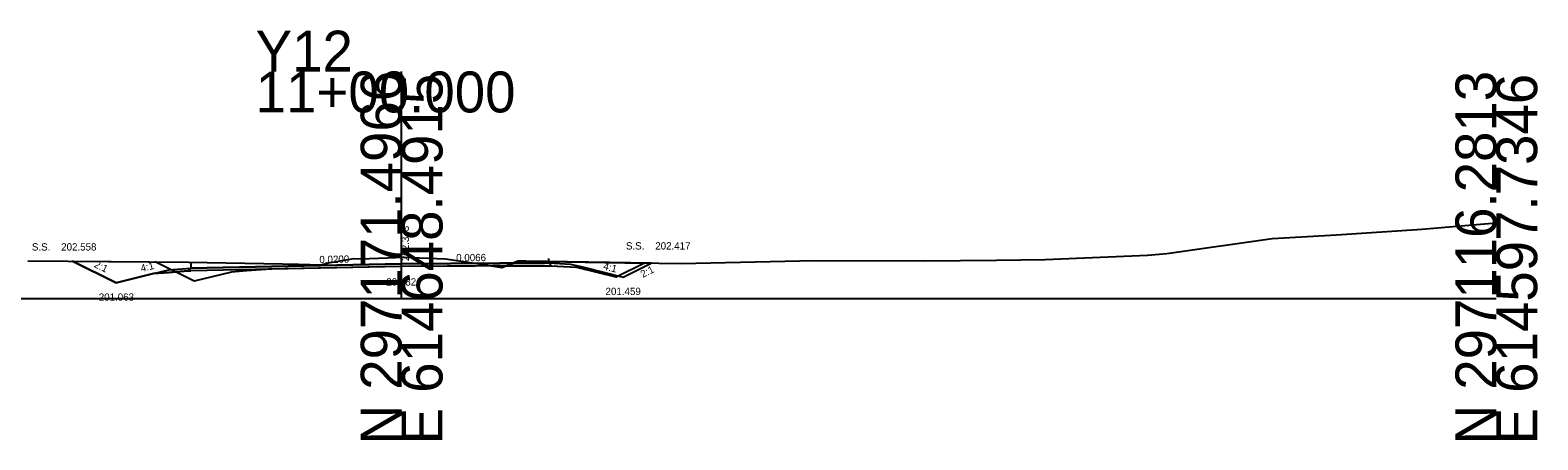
# Model space of a CAD drawing. Extents: x 517327 to 517505, y 114839 to 117367.
# Drawn here: x 517401.9 to 517505.2, y 117338.7 to 117366.8 of the extents above; entities that cross this region are included whole.
import ezdxf

# ---------------------------------------------------------------- set-up
doc = ezdxf.new("R2010")
doc.units = 0
for name, color, linetype in [('Exist XS Ground Line', 7, 'Continuous'), ('Old_Level_3', 7, 'Continuous'), ('Old_Level_5', 7, 'Continuous'), ('Old_Level_59', 7, 'Continuous'), ('Old_Level_63', 7, 'Continuous'), ('Prop XS Dump Level', 7, 'Continuous'), ('Prop XS Earthwork Shape', 7, 'Continuous'), ('Prop XS Elevation Labels', 7, 'Continuous'), ('Prop XS EOT Tick Mark', 7, 'Continuous'), ('Prop XS Finish Grade', 7, 'Continuous'), ('Prop XS Finish Grade Earthwork', 7, 'Continuous'), ('Prop XS Finish Grade Pavement', 7, 'Continuous'), ('Prop XS Hydro Elevations', 7, 'Continuous'), ('Prop XS Pvmt Edge Slope', 7, 'Continuous'), ('Prop XS Side Slope Text', 7, 'Continuous'), ('Prop XS Subgrade Earthwork', 7, 'Continuous'), ('Prop XS Suitable Common Exc Shape', 7, 'Continuous')]:
    doc.layers.add(name, color=color, linetype=linetype)

msp = doc.modelspace()

# ---------------------------------------------------------------- linework, layer by layer
at = {"layer": 'Exist XS Ground Line'}
for p, q in [((517497.25, 117353.11), (517502.36, 117353.55)), ((517479.79, 117351.44), (517487, 117352.47)), ((517487, 117352.47), (517491.4, 117352.72)), ((517491.4, 117352.72), (517497.25, 117353.11)), ((517479.27, 117351.39), (517479.79, 117351.44)), ((517401.76, 117350.95), (517412.76, 117350.85)), ((517412.76, 117350.85), (517419.2, 117350.74)), ((517419.2, 117350.74), (517420.3, 117350.71)), ((517420.3, 117350.71), (517421.87, 117350.67)), ((517421.87, 117350.67), (517422.32, 117350.8)), ((517422.32, 117350.8), (517424.09, 117351.11)), ((517424.09, 117351.11), (517424.56, 117351.08)), ((517424.56, 117351.08), (517426.37, 117351.15)), ((517426.37, 117351.15), (517427.51, 117351.19)), ((517427.51, 117351.19), (517428.61, 117351.15)), ((517428.61, 117351.15), (517430.36, 117351.09)), ((517430.36, 117351.09), (517432.35, 117350.78)), ((517432.35, 117350.78), (517434.22, 117350.49)), ((517434.22, 117350.49), (517435.35, 117350.93)), ((517435.35, 117350.93), (517435.88, 117350.92)), ((517435.88, 117350.92), (517446.52, 117350.75)), ((517446.52, 117350.75), (517455.64, 117350.96)), ((517455.64, 117350.96), (517463.16, 117350.94)), ((517463.16, 117350.94), (517468.12, 117351)), ((517468.12, 117351), (517471.46, 117351.04)), ((517471.46, 117351.04), (517478.47, 117351.34)), ((517478.47, 117351.34), (517479.27, 117351.39))]:
    msp.add_line(p, q, dxfattribs=at)
at = {"layer": 'Old_Level_63'}
for p, q in [((517427.36, 117348.36), (517427.36, 117363.92)), ((517352.36, 117348.36), (517427.36, 117348.36)), ((517427.36, 117348.36), (517502.36, 117348.36))]:
    msp.add_line(p, q, dxfattribs=at)
at = {"layer": 'Prop XS Dump Level'}
for p, q in [((517412.91, 117350.45), (517427.36, 117350.74)), ((517427.36, 117350.74), (517437.44, 117350.8))]:
    msp.add_line(p, q, dxfattribs=at)
at = {"layer": 'Prop XS Earthwork Shape'}
for points in [[(517404.82, 117350.92), (517412.76, 117350.85), (517419.2, 117350.74), (517420.3, 117350.71), (517421.87, 117350.67), (517422.32, 117350.8), (517424.09, 117351.11), (517424.56, 117351.08), (517426.37, 117351.15), (517427.51, 117351.19), (517428.61, 117351.15), (517430.36, 117351.09), (517432.35, 117350.78), (517433.58, 117350.59), (517427.36, 117350.55), (517412.91, 117350.26), (517412.72, 117350.25), (517411.41, 117350.15), (517410.36, 117350.07), (517407.81, 117349.43)], [(517434.22, 117350.49), (517434.49, 117350.59), (517433.58, 117350.59)], [(517437.44, 117350.61), (517437.62, 117350.61), (517438.94, 117350.54), (517439.84, 117350.5), (517442.54, 117349.82), (517444.45, 117350.78), (517435.88, 117350.92), (517435.35, 117350.93), (517434.49, 117350.59)]]:
    msp.add_lwpolyline(points, close=True, dxfattribs=at)
at = {"layer": 'Prop XS EOT Tick Mark'}
for p, q in [((517412.91, 117350.75), (517412.91, 117350.45)), ((517437.44, 117350.8), (517437.44, 117351.11))]:
    msp.add_line(p, q, dxfattribs=at)
at = {"layer": 'Prop XS Finish Grade'}
for p, q in [((517411.41, 117350.33), (517412.91, 117350.45)), ((517437.44, 117350.8), (517438.94, 117350.72)), ((517438.94, 117350.72), (517439.84, 117350.5)), ((517410.36, 117350.07), (517411.41, 117350.33))]:
    msp.add_line(p, q, dxfattribs=at)
at = {"layer": 'Prop XS Finish Grade Earthwork'}
for p, q in [((517404.82, 117350.92), (517407.81, 117349.43)), ((517439.84, 117350.5), (517442.54, 117349.82)), ((517442.54, 117349.82), (517444.45, 117350.78)), ((517407.81, 117349.43), (517410.36, 117350.07))]:
    msp.add_line(p, q, dxfattribs=at)
at = {"layer": 'Prop XS Finish Grade Pavement'}
for p, q in [((517427.36, 117350.74), (517412.91, 117350.45)), ((517437.44, 117350.8), (517427.36, 117350.74))]:
    msp.add_line(p, q, dxfattribs=at)
at = {"layer": 'Prop XS Pvmt Edge Slope'}
for p, q in [((517412.72, 117350.25), (517412.91, 117350.45)), ((517437.44, 117350.8), (517437.62, 117350.61))]:
    msp.add_line(p, q, dxfattribs=at)
at = {"layer": 'Prop XS Subgrade Earthwork'}
for p, q in [((517427.36, 117350.55), (517412.91, 117350.26)), ((517437.44, 117350.61), (517427.36, 117350.55)), ((517437.44, 117350.61), (517437.62, 117350.61)), ((517437.62, 117350.61), (517438.94, 117350.54)), ((517438.94, 117350.54), (517439.84, 117350.5)), ((517410.36, 117350.07), (517411.41, 117350.15)), ((517411.41, 117350.15), (517412.72, 117350.25)), ((517412.72, 117350.25), (517412.91, 117350.26))]:
    msp.add_line(p, q, dxfattribs=at)
at = {"layer": 'Prop XS Suitable Common Exc Shape'}
for points in [[(517433.58, 117350.59), (517427.36, 117350.55), (517418.25, 117350.37), (517418.06, 117350.36), (517416.75, 117350.26), (517415.7, 117350.17), (517413.15, 117349.54), (517410.47, 117350.87), (517412.76, 117350.85), (517419.2, 117350.74), (517420.3, 117350.71), (517421.87, 117350.67), (517422.32, 117350.8), (517424.09, 117351.11), (517424.56, 117351.08), (517426.37, 117351.15), (517427.51, 117351.19), (517428.61, 117351.15), (517430.36, 117351.09), (517432.35, 117350.78)], [(517434.22, 117350.49), (517434.49, 117350.59), (517433.58, 117350.59)], [(517435.88, 117350.92), (517444, 117350.79), (517442.06, 117349.82), (517439.37, 117350.49), (517438.46, 117350.54), (517437.15, 117350.61), (517436.96, 117350.61), (517434.49, 117350.59), (517435.35, 117350.93)]]:
    msp.add_lwpolyline(points, close=True, dxfattribs=at)

# ---------------------------------------------------------------- texts
at = {"layer": 'Old_Level_3'}
for rotation, p in [(14.0362, (517409.54, 117350.17)), (345.9638, (517441.14, 117350.36))]:
    msp.add_text('4:1', height=0.5, rotation=rotation, dxfattribs=at).set_placement(p)
at = {"layer": 'Old_Level_5'}
for s, rotation, p in [('0.0066', 0.3766, (517431.1, 117350.91)), ('0.0200', 1.1458, (517421.73, 117350.78))]:
    msp.add_text(s, height=0.5, rotation=rotation, dxfattribs=at).set_placement(p)
at = {"layer": 'Old_Level_59'}
msp.add_text(' 202.373', height=0.5, rotation=90, dxfattribs=at).set_placement((517427.86, 117350.74))
msp.add_text(' 202.373', height=0.5, rotation=90, dxfattribs=at).set_placement((517427.86, 117350.74))
msp.add_text(' 202.373', height=0.5, rotation=90, dxfattribs=at).set_placement((517427.86, 117350.74))
msp.add_text('202.82', height=0.5, dxfattribs=at).set_placement((517426.31, 117349.25))
at = {"layer": 'Old_Level_63'}
for s, p in [('Y12', (517417.36, 117363.92)), ('11+00.000', (517417.36, 117361.12))]:
    msp.add_text(s, height=2.8, dxfattribs=at).set_placement(p)
for s, p in [('N 297171.4966', (517427.36, 117338.36)), ('N 297116.2813', (517502.36, 117338.36)), ('E 614648.4915', (517430.16, 117338.36)), ('E 614597.7346', (517505.16, 117338.36))]:
    msp.add_text(s, height=2.8, rotation=90, dxfattribs=at).set_placement(p)
at = {"layer": 'Prop XS Elevation Labels'}
for p in [(517438.94, 117350.71), (517411.41, 117350.32)]:
    msp.add_text('Case1', height=0.0122, dxfattribs=at).set_placement(p)
at = {"layer": 'Prop XS Hydro Elevations'}
for s, p in [('S.S.    202.558', (517402.03, 117351.65)), ('S.S.    202.417', (517442.73, 117351.72))]:
    msp.add_text(s, height=0.5, dxfattribs=at).set_placement(p)
at = {"layer": 'Prop XS Side Slope Text'}
for rotation, p in [(333.435, (517406.25, 117350.54)), (26.5651, (517443.88, 117349.77))]:
    msp.add_text('2:1', height=0.5, rotation=rotation, dxfattribs=at).set_placement(p)
for s, p in [('201.063', (517406.61, 117348.21)), ('201.459', (517441.33, 117348.6))]:
    msp.add_text(s, height=0.5, dxfattribs=at).set_placement(p)

doc.saveas('drawing.dxf')
